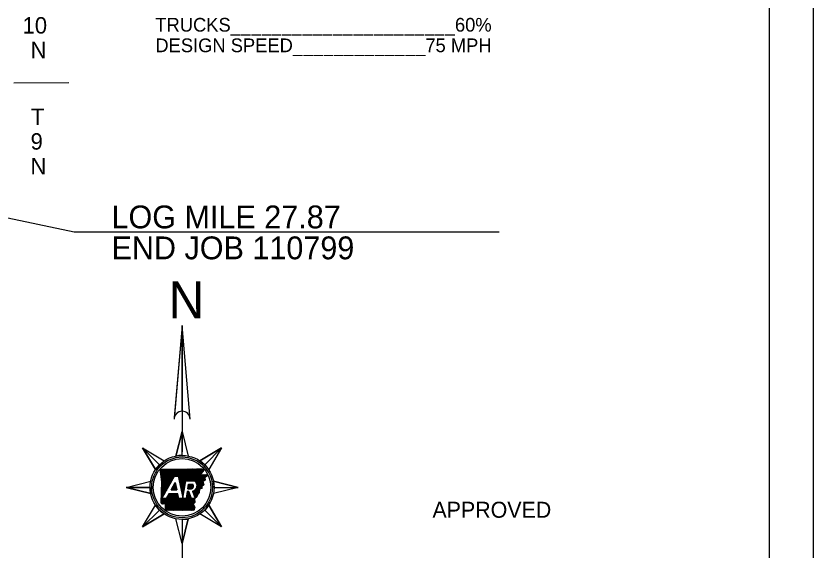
# Model space of a CAD drawing. Extents: x -117616 to 64730, y 54117 to 789866.
# Drawn here: x 63857 to 64730, y 54581 to 55166 of the extents above; entities that cross this region are included whole.
import ezdxf

# ---------------------------------------------------------------- set-up
doc = ezdxf.new("R2010")
doc.units = 0
for name, color, linetype in [('Default', 7, 'Continuous'), ('R_Border', 7, 'Continuous'), ('R_Border PE', 7, 'Continuous'), ('R_Dimension', 7, 'Continuous'), ('R_Draft', 7, 'Continuous'), ('R_No Plot', 7, 'Continuous'), ('R_Water Annot', 7, 'Continuous')]:
    doc.layers.add(name, color=color, linetype=linetype)

msp = doc.modelspace()

# ---------------------------------------------------------------- linework, layer by layer
at = {"layer": 'R_Border'}
msp.add_line((64682.04, 54157.32), (64682.04, 56211.92), dxfattribs=at)
at = {"layer": 'R_Dimension'}
msp.add_line((63914.85, 55092.6), (63854.85, 55092.36), dxfattribs=at)
msp.add_lwpolyline([(63249.43, 55071.04), (63920.83, 54929.5), (64386.07, 54929.5)], dxfattribs=at)
at = {"layer": 'R_Draft'}
for p, q in [((64038.99, 54826.97), (64030.37, 54726.08)), ((64038.99, 54826.97), (64038.99, 54688.8)), ((64038.99, 54733.35), (64038.99, 54826.97)), ((64030.49, 54727.49), (64030.88, 54727.88)), ((64030.53, 54728.03), (64031.33, 54728.83)), ((64038.99, 54711.23), (64032.17, 54684.31)), ((64038.99, 54684.98), (64038.99, 54711.23)), ((63995.68, 54693.29), (64014.24, 54674.73)), ((64014.24, 54674.73), (63995.68, 54693.29)), ((63995.68, 54693.29), (64009.9, 54669.43)), ((64082.3, 54693.29), (64058.45, 54679.07)), ((64063.74, 54674.73), (64082.3, 54693.29)), ((64063.74, 54674.73), (64082.3, 54693.29)), ((64016.89, 54637.72), (64030.69, 54662.1)), ((64030.69, 54662.1), (64034.8, 54662.1)), ((63977.74, 54649.98), (64003.99, 54649.98)), ((64003.99, 54649.98), (63977.74, 54649.98)), ((63977.74, 54649.98), (64004.66, 54643.16)), ((64027.04, 54647.29), (64031.56, 54655.27)), ((64043.13, 54657.02), (64052.72, 54657.02)), ((64045.21, 54648.37), (64049.32, 54648.37)), ((64046.12, 54653.57), (64050.62, 54653.57)), ((64100.24, 54649.98), (64073.32, 54656.79)), ((64073.99, 54649.98), (64100.24, 54649.98)), ((64073.99, 54649.98), (64100.24, 54649.98)), ((64024.52, 54642.83), (64021.62, 54637.72)), ((64034.22, 54642.83), (64024.52, 54642.83)), ((64027.04, 54647.29), (64033.27, 54647.29)), ((64046.37, 54645.47), (64044.7, 54645.47)), ((64049.23, 54637.72), (64046.37, 54645.47)), ((64050.43, 54645.89), (64053.44, 54637.72)), ((64021.62, 54637.72), (64016.89, 54637.72)), ((64043.35, 54637.72), (64035.32, 54637.72)), ((64053.44, 54637.72), (64049.23, 54637.72)), ((63995.68, 54606.67), (64014.24, 54625.23)), ((64014.24, 54625.23), (63995.68, 54606.67)), ((64063.74, 54625.23), (64082.3, 54606.67)), ((64063.74, 54625.23), (64082.3, 54606.67)), ((64082.3, 54606.67), (64068.08, 54630.52)), ((63995.68, 54606.67), (64019.53, 54620.88)), ((64038.99, 54588.73), (64045.81, 54615.65)), ((64038.99, 54614.98), (64038.99, 54614.98)), ((64038.99, 54614.98), (64038.99, 54502.93)), ((64038.99, 54614.98), (64038.99, 54588.73))]:
    msp.add_line(p, q, dxfattribs=at)
for points in [[(64047.74, 54724.6), (64038.99, 54826.97), (64030.24, 54724.6)], [(64032.17, 54684.31), (64038.99, 54711.23), (64045.81, 54684.31)], [(64009.9, 54669.43), (63995.68, 54693.29), (64019.53, 54679.07)], [(64058.45, 54679.07), (64082.3, 54693.29), (64068.08, 54669.43)], [(64015.09, 54670.01), (64028.75, 54670), (64040.74, 54670.03), (64054.88, 54670.25), (64061.43, 54670.4)], [(64016.08, 54633.06), (64016.84, 54655.97), (64015.09, 54670.01)], [(64034.8, 54662.1), (64039.88, 54638.37), (64043.13, 54657.02)], [(64065.72, 54664.13), (64066.9, 54662.89), (64063.96, 54660.47), (64064.27, 54658.02), (64061.75, 54656.36), (64062.61, 54652.6), (64060.66, 54650.82), (64060.49, 54648.89), (64058.12, 54648.04), (64057.75, 54644.39), (64056.05, 54642.57), (64055.23, 54639.82), (64052.75, 54637.55), (64052.94, 54633.55), (64051.25, 54631.66), (64052.79, 54628.23), (64051.73, 54624.82)], [(64059.4, 54663.8), (64065.81, 54664.13)], [(64004.66, 54643.16), (63977.74, 54649.98), (64004.66, 54656.79)], [(64031.56, 54655.27), (64033.27, 54647.29)], [(64045.21, 54648.37), (64046.12, 54653.57)], [(64073.32, 54656.79), (64100.24, 54649.98), (64073.32, 54643.16)], [(64035.32, 54637.72), (64034.22, 54642.83)], [(64044.7, 54645.47), (64043.35, 54637.72)], [(64051.73, 54624.82), (64020.77, 54624.87), (64020.75, 54631.7)], [(64019.53, 54620.88), (63995.68, 54606.67), (64009.9, 54630.52)], [(64068.08, 54630.52), (64082.3, 54606.67), (64058.45, 54620.88)], [(64045.81, 54615.65), (64038.99, 54588.73), (64032.17, 54615.65)]]:
    msp.add_lwpolyline(points, dxfattribs=at)
for radius in [35, 31.5]:
    msp.add_circle((64038.99, 54649.98), radius, dxfattribs=at)
for centre, radius, start, end in [((64038.99, 54724.6), 8.75, 0, 180), ((64038.99, 54724.6), 8.75, 90, 170.22959), ((64038.99, 54649.98), 35, 90, 101.22909), ((64038.99, 54649.98), 35, 135, 146.22909), ((64038.99, 54649.98), 35, 45, 56.22909), ((64038.99, 54649.98), 35, 180, 191.22909), ((64048.34, 54651.38), 3.17, 288.12683, 43.89016), ((64049.15, 54651.95), 6.2, 281.86262, 54.87052), ((64038.99, 54649.98), 35, 0, 11.22909), ((64038.99, 54649.98), 35, 225, 236.22909), ((64038.99, 54649.98), 35, 315, 326.22909), ((64038.99, 54649.98), 35, 270, 281.22909)]:
    msp.add_arc(centre, radius, start, end, dxfattribs=at)
for points in [[(64061.43, 54670.4), (64061.47, 54670.03), (64061.59, 54669.84), (64061.61, 54669.48), (64061.75, 54669.33), (64062, 54669.18), (64062.22, 54668.93), (64062.27, 54668.64), (64062.2, 54668.35), (64062.18, 54668.02), (64062.15, 54667.73), (64062.1, 54667.47), (64061.89, 54667.26), (64061.7, 54667.11), (64061.52, 54666.93), (64061.4, 54666.74), (64061.18, 54666.54), (64060.96, 54666.33), (64060.78, 54666.14), (64060.6, 54665.91), (64060.52, 54665.65), (64060.32, 54665.46), (64060.17, 54665.29), (64059.97, 54665.06), (64059.87, 54664.83), (64059.67, 54664.57), (64059.63, 54664.32), (64059.5, 54664.12), (64059.5, 54664.08)], [(64020.75, 54631.7), (64020.79, 54631.68), (64020.63, 54631.79), (64020.41, 54631.9), (64020.16, 54631.92), (64019.85, 54631.96), (64019.59, 54631.99), (64019.32, 54632.17), (64019.03, 54631.98), (64018.71, 54631.84), (64018.52, 54632), (64018.28, 54631.89), (64018.11, 54631.95), (64017.81, 54631.74), (64017.54, 54631.82), (64017.33, 54631.76), (64017.08, 54631.77), (64017.03, 54632.06), (64016.78, 54632.1), (64016.57, 54632.22), (64016.43, 54632.51), (64016.33, 54632.74), (64016.08, 54633.06)]]:
    msp.add_spline(points, degree=3, dxfattribs=at)
at = {"layer": 'R_No Plot'}
msp.add_lwpolyline([(61396.16, 56250.87), (64729.56, 56250.87), (64729.56, 54117.5), (61396.16, 54117.5)], close=True, dxfattribs=at)
at = {"layer": 'R_Water Annot'}
for p, q in [((64015.13, 54669.7), (64015.44, 54670.01)), ((64015.24, 54668.82), (64016.43, 54670.01)), ((64015.35, 54667.94), (64017.42, 54670.01)), ((64015.46, 54667.06), (64018.41, 54670.01)), ((64015.57, 54666.18), (64019.4, 54670.01)), ((64015.68, 54665.3), (64020.39, 54670.01)), ((64015.79, 54664.42), (64021.38, 54670.01)), ((64015.9, 54663.54), (64022.37, 54670.01)), ((64016.01, 54662.66), (64023.36, 54670.01)), ((64016.12, 54661.78), (64024.35, 54670.01)), ((64016.23, 54660.9), (64025.33, 54670.01)), ((64016.34, 54660.02), (64026.32, 54670.01)), ((64016.45, 54659.14), (64027.31, 54670)), ((64016.56, 54658.26), (64028.3, 54670)), ((64016.59, 54648.39), (64038.22, 54670.02)), ((64016.63, 54649.42), (64037.23, 54670.02)), ((64016.66, 54650.44), (64036.24, 54670.02)), ((64016.67, 54657.38), (64029.29, 54670.01)), ((64016.69, 54651.46), (64035.25, 54670.02)), ((64016.73, 54652.49), (64034.25, 54670.02)), ((64016.76, 54653.51), (64033.26, 54670.01)), ((64016.78, 54656.5), (64030.29, 54670.01)), ((64016.79, 54654.54), (64032.27, 54670.01)), ((64016.83, 54655.56), (64031.28, 54670.01)), ((64031.29, 54662.1), (64039.21, 54670.03)), ((64032.28, 54662.1), (64040.21, 54670.03)), ((64033.27, 54662.1), (64041.2, 54670.04)), ((64034.26, 54662.1), (64042.21, 54670.05)), ((64034.88, 54661.73), (64043.22, 54670.07)), ((64035.05, 54660.92), (64044.22, 54670.08)), ((64035.23, 54660.1), (64045.23, 54670.1)), ((64035.4, 54659.28), (64046.23, 54670.11)), ((64035.58, 54658.47), (64047.24, 54670.13)), ((64035.75, 54657.65), (64048.24, 54670.15)), ((64035.93, 54656.84), (64049.25, 54670.16)), ((64036.1, 54656.02), (64050.25, 54670.18)), ((64036.27, 54655.21), (64051.26, 54670.19)), ((64036.45, 54654.39), (64052.27, 54670.21)), ((64036.62, 54653.58), (64053.27, 54670.22)), ((64036.8, 54652.76), (64054.28, 54670.24)), ((64036.97, 54651.95), (64055.29, 54670.26)), ((64037.15, 54651.13), (64056.3, 54670.28)), ((64044.02, 54657.02), (64057.31, 54670.31)), ((64045.01, 54657.02), (64058.33, 54670.33)), ((64046, 54657.02), (64059.34, 54670.35)), ((64046.99, 54657.02), (64060.35, 54670.38)), ((64047.98, 54657.02), (64061.37, 54670.4)), ((64048.97, 54657.02), (64061.59, 54669.63)), ((64049.96, 54657.02), (64062.07, 54669.12)), ((64050.95, 54657.02), (64062.19, 54668.26)), ((64016.52, 54646.35), (64028.62, 54658.44)), ((64016.56, 54647.37), (64029.92, 54660.73)), ((64051.94, 54657.02), (64059.93, 54665.01)), ((64052.84, 54656.93), (64059.74, 54663.82)), ((64053.38, 54656.48), (64060.78, 54663.88)), ((64053.87, 54655.97), (64061.83, 54663.93)), ((64054.29, 54655.41), (64062.87, 54663.98)), ((64054.66, 54654.78), (64063.91, 54664.04)), ((64054.96, 54654.1), (64064.96, 54664.09)), ((64055.12, 54650.3), (64064.11, 54659.28)), ((64055.19, 54653.34), (64065.9, 54664.04)), ((64055.33, 54652.48), (64066.36, 54663.51)), ((64055.33, 54651.5), (64064, 54660.16)), ((64063, 54657.18), (64064.22, 54658.41)), ((64065.92, 54662.08), (64066.82, 54662.98)), ((64016.39, 54642.25), (64023.45, 54649.32)), ((64016.42, 54643.27), (64024.75, 54651.6)), ((64016.46, 54644.3), (64026.04, 54653.88)), ((64016.49, 54645.32), (64027.33, 54656.16)), ((64027.09, 54647.29), (64032.18, 54652.38)), ((64028.08, 54647.29), (64032.35, 54651.56)), ((64028.27, 54649.46), (64032, 54653.19)), ((64029.07, 54647.29), (64032.53, 54650.74)), ((64029.57, 54651.74), (64031.83, 54654.01)), ((64030.06, 54647.29), (64032.7, 54649.93)), ((64030.86, 54654.02), (64031.66, 54654.82)), ((64031.05, 54647.29), (64032.88, 54649.11)), ((64037.32, 54650.31), (64042.94, 54655.93)), ((64037.5, 54649.5), (64042.73, 54654.73)), ((64037.67, 54648.68), (64042.52, 54653.53)), ((64037.84, 54647.87), (64042.31, 54652.34)), ((64038.02, 54647.05), (64042.1, 54651.14)), ((64038.19, 54646.24), (64041.89, 54649.94)), ((64038.37, 54645.42), (64041.69, 54648.74)), ((64045.22, 54648.37), (64050.42, 54653.57)), ((64045.42, 54649.56), (64049.43, 54653.57)), ((64045.63, 54650.76), (64048.44, 54653.57)), ((64045.83, 54651.96), (64047.45, 54653.57)), ((64046.04, 54653.15), (64046.46, 54653.57)), ((64046.21, 54648.37), (64050.97, 54653.13)), ((64047.19, 54648.37), (64051.31, 54652.48)), ((64048.18, 54648.37), (64051.49, 54651.67)), ((64049.17, 54648.37), (64051.41, 54650.6)), ((64051.04, 54644.23), (64062.01, 54655.21)), ((64051.3, 54643.51), (64062.2, 54654.4)), ((64051.57, 54642.79), (64062.38, 54653.6)), ((64051.84, 54642.06), (64062.57, 54652.79)), ((64054.26, 54648.45), (64061.83, 54656.01)), ((64059.18, 54648.42), (64060.57, 54649.81)), ((64016.25, 54638.15), (64018.28, 54640.19)), ((64016.29, 54639.18), (64019.58, 54642.47)), ((64016.32, 54640.2), (64020.87, 54644.75)), ((64016.35, 54641.23), (64022.16, 54647.03)), ((64016.47, 54632.43), (64026.87, 54642.83)), ((64017.05, 54632.03), (64027.86, 54642.83)), ((64017.77, 54631.75), (64028.85, 54642.83)), ((64018.94, 54631.93), (64029.84, 54642.83)), ((64019.95, 54631.95), (64030.83, 54642.83)), ((64020.72, 54631.74), (64031.82, 54642.83)), ((64020.76, 54629.79), (64033.8, 54642.83)), ((64020.76, 54630.78), (64032.81, 54642.83)), ((64020.76, 54628.8), (64034.32, 54642.36)), ((64020.76, 54627.82), (64034.5, 54641.55)), ((64020.77, 54626.83), (64034.67, 54640.73)), ((64020.77, 54625.84), (64034.84, 54639.92)), ((64022.75, 54639.7), (64025.88, 54642.83)), ((64024.04, 54641.98), (64024.89, 54642.83)), ((64030.67, 54624.85), (64047.69, 54641.88)), ((64031.66, 54624.85), (64047.96, 54641.16)), ((64032.04, 54647.29), (64033.05, 54648.3)), ((64032.64, 54624.85), (64048.23, 54640.43)), ((64033.03, 54647.29), (64033.23, 54647.48)), ((64033.63, 54624.85), (64048.5, 54639.71)), ((64038.54, 54644.61), (64041.48, 54647.54)), ((64038.72, 54643.79), (64041.27, 54646.34)), ((64038.89, 54642.98), (64041.06, 54645.14)), ((64039.07, 54642.16), (64040.85, 54643.94)), ((64039.24, 54641.34), (64040.64, 54642.74)), ((64039.42, 54640.53), (64040.43, 54641.55)), ((64039.59, 54639.71), (64040.22, 54640.35)), ((64043.52, 54638.7), (64047.43, 54642.6)), ((64043.73, 54639.9), (64047.16, 54643.32)), ((64043.94, 54641.1), (64046.89, 54644.05)), ((64044.15, 54642.29), (64046.63, 54644.77)), ((64044.36, 54643.49), (64046.34, 54645.47)), ((64044.57, 54644.69), (64045.35, 54645.47)), ((64050.5, 54645.68), (64050.8, 54645.98)), ((64050.77, 54644.95), (64052.65, 54646.84)), ((64052.11, 54641.34), (64058.04, 54647.28)), ((64052.37, 54640.62), (64057.93, 54646.18)), ((64052.64, 54639.89), (64057.82, 54645.08)), ((64052.91, 54639.17), (64055.94, 54642.21)), ((64053.17, 54638.45), (64055.52, 54640.79)), ((64016.1, 54633.05), (64020.76, 54637.72)), ((64016.12, 54634.06), (64019.77, 54637.72)), ((64016.15, 54635.08), (64018.78, 54637.72)), ((64016.18, 54636.11), (64017.79, 54637.72)), ((64016.22, 54637.13), (64016.99, 54637.9)), ((64020.78, 54624.87), (64035.02, 54639.1)), ((64021.77, 54624.87), (64035.19, 54638.29)), ((64022.76, 54624.86), (64035.61, 54637.72)), ((64023.75, 54624.86), (64036.6, 54637.72)), ((64024.74, 54624.86), (64037.59, 54637.72)), ((64025.73, 54624.86), (64038.58, 54637.72)), ((64026.71, 54624.86), (64039.57, 54637.72)), ((64027.7, 54624.86), (64040.56, 54637.72)), ((64028.69, 54624.85), (64041.55, 54637.72)), ((64029.68, 54624.85), (64042.54, 54637.72)), ((64034.62, 54624.85), (64048.76, 54638.99)), ((64035.61, 54624.84), (64049.03, 54638.26)), ((64036.6, 54624.84), (64049.47, 54637.72)), ((64037.59, 54624.84), (64050.46, 54637.72)), ((64038.57, 54624.84), (64051.45, 54637.72)), ((64039.56, 54624.84), (64052.44, 54637.72)), ((64039.76, 54638.9), (64040.01, 54639.15)), ((64040.55, 54624.84), (64052.77, 54637.06)), ((64041.54, 54624.83), (64052.82, 54636.11)), ((64042.53, 54624.83), (64052.86, 54635.17)), ((64043.52, 54624.83), (64052.91, 54634.22)), ((64044.5, 54624.83), (64051.28, 54631.6)), ((64045.49, 54624.83), (64051.59, 54630.92)), ((64046.48, 54624.83), (64051.89, 54630.24)), ((64047.47, 54624.82), (64052.2, 54629.55)), ((64048.46, 54624.82), (64052.5, 54628.87)), ((64049.45, 54624.82), (64052.76, 54628.13)), ((64050.43, 54624.82), (64052.31, 54626.69)), ((64051.42, 54624.82), (64051.86, 54625.26))]:
    msp.add_line(p, q, dxfattribs=at)
msp.add_circle((64038.99, 54649.98), 33.25, dxfattribs=at)

# ---------------------------------------------------------------- texts
at = {"layer": 'Default'}
for s, p in [('10', (63864.44, 55146.5)), ('N', (63873.15, 55119.5)), ('T', (63873.59, 55046.5)), ('9', (63873.17, 55019.5)), ('N', (63873.08, 54992.5))]:
    msp.add_text(s, height=18, dxfattribs=at).set_placement(p)
at = {"layer": 'R_Border PE'}
msp.add_text('APPROVED', height=17.496, dxfattribs=at).set_placement((64313, 54616.75))
at = {"layer": 'R_Dimension'}
for s, p in [('LOG MILE 27.87', (63961.75, 54933.38)), ('END JOB 110799', (63961.75, 54899.52))]:
    msp.add_text(s, height=25, rotation=0.0006, dxfattribs=at).set_placement(p)
at = {"layer": 'R_Draft'}
for s, height, p in [('TRUCKS______________________60%', 15, (64009.74, 55148.63)), ('DESIGN SPEED_____________75 MPH', 15, (64009.74, 55126.13)), ('N', 40.39, (64024.23, 54834.92)), ('DWB 7-27-17', 0.6806, (64036.85, 54617.89))]:
    msp.add_text(s, height=height, dxfattribs=at).set_placement(p)

doc.saveas('drawing.dxf')
